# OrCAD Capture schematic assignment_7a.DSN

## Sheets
1 PAGE1: size A
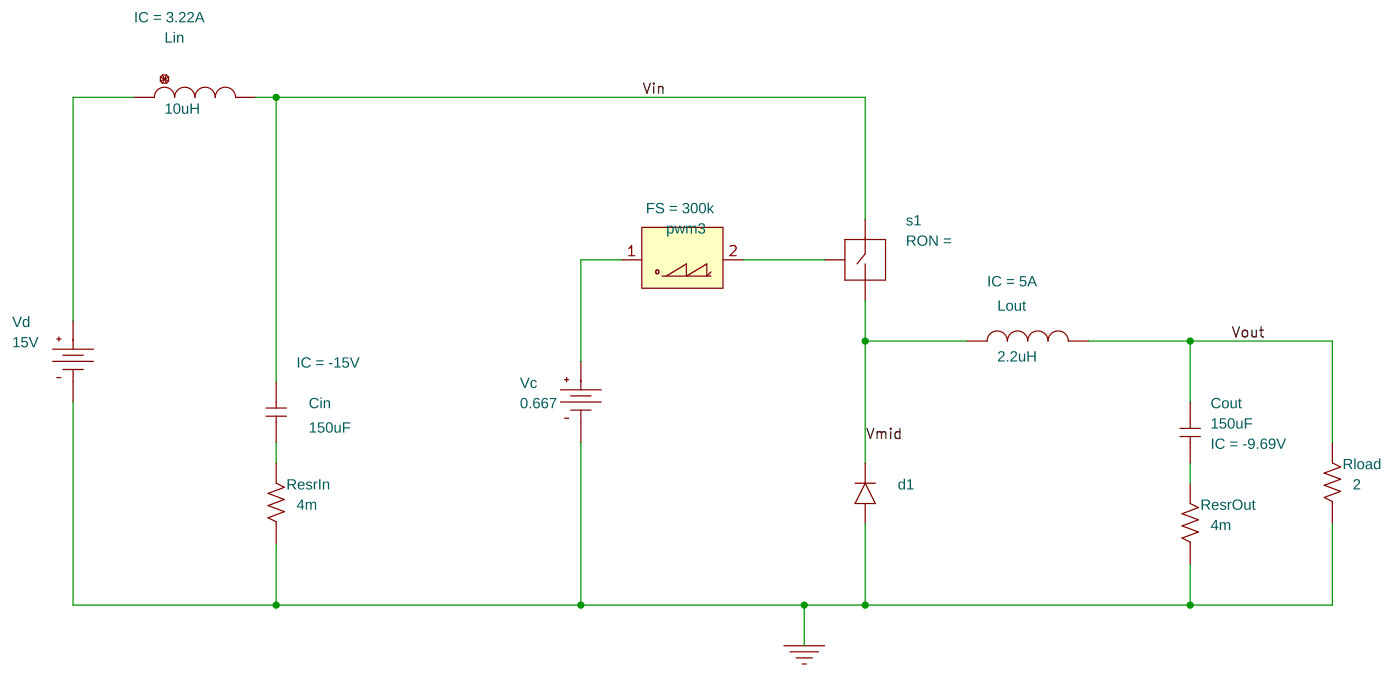
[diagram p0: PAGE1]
2 PAGE1 (2)
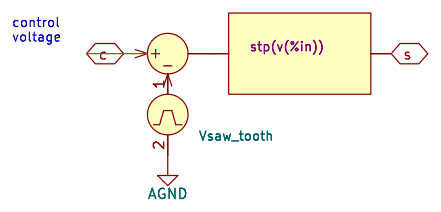
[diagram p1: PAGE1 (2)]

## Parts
sheet PAGE1 (2)
ABM13  abm1
DIFF1  diff
Vsaw_tooth  VPULSE
sheet PAGE1
Cin  150uF  [RAD/CK05]
Cout  150uF  [RAD/CK05]
d1  d
Lin  10uH  [DISC/.350x.175/LS.200x.100/.034]
Lout  2.2uH  [L3216C]
pwm3  PWM_ST
ResrIn  4m  [AX/RC05]
ResrOut  4m  [AX/RC05]
Rload  2  [AX/RC05]
s1  s
Vc  VDC
Vd  VDC

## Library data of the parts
ABM13 = ABM1: EXP1: stp(v(%in))
DIFF1 = DIFF
Vsaw_tooth = VPULSE: PER: {1/@FS}; PW: 0.01us; TD: 0; TF: 0.01us; TR: {1/@FS - 0.02us}; V1: 0V; V2: 1V
Cin = C: IC: -15V
Cout = C: IC: -9.69V
d1 = diode
Lin = L_v2: IC: 3.22A
Lout = L: IC: 5A
pwm3 = PWM_ST: FS: 300k
ResrIn ResrOut Rload = R
s1 = v-switch
Vc = VDC: DC: 0.667
Vd = VDC: DC: 15V

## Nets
AGND: Vsaw_tooth.2(-)
Vin: Cin.2 Lin.2 s1.2(s+)
0: d1.1(A) ResrIn.1 ResrOut.1 Rload.1 Vc.1(-) Vd.1(-)
c: DIFF1.3(IN2)
s: ABM13.2(OUT)
Vmid: d1.2(K) Lout.1 s1.3(s-)
Vout: Cout.2 Lout.2 Rload.2
N19478: pwm3.1(c) Vc.0(+)
N19498: Lin.1 Vd.0(+)
N19608: pwm3.2(s) s1.1(vc+)
N19700: Cout.1 ResrOut.2
N19708: Cin.1 ResrIn.2

Not connected (* = marked no-connect by the designer): ABM13 1(IN); DIFF1 1(IN1) 5(OUT); Vsaw_tooth 1(+)

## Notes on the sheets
sheet 2
- control
  voltage
